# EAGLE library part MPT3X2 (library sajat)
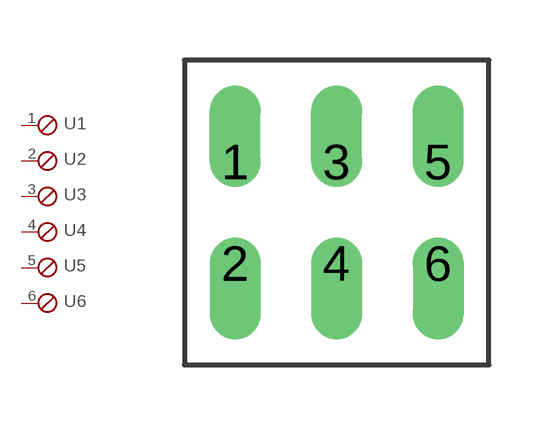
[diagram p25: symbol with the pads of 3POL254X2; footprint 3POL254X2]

Designator prefix -; gates 1=SKB 2=SKB 3=SKB 4=SKB 5=SKB 6=SKB

## MPT3X2  [3POL254X2]
1  1:1  pas
2  2:1  pas
3  3:1  pas
4  4:1  pas
5  5:1  pas
6  6:1  pas

## Footprint 3POL254X2 (pad centres in mm)
drill 0.4 pad 1.27 offset: 1 -2.54,1.27; 2 -2.54,-1.27; 3 0,1.27; 4 0,-1.27; 5 2.54,1.27; 6 2.54,-1.27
